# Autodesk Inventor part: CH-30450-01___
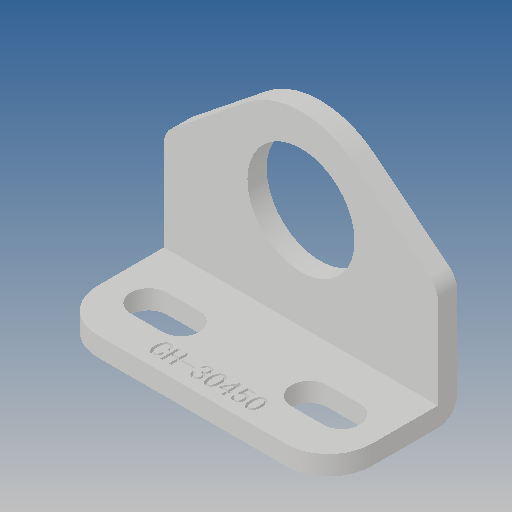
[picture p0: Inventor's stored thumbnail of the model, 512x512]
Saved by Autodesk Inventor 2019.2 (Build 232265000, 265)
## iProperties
Created: 2010-06
Part Number: CH-30450-01___
Material: Ogólny
Document SubType Name: Modeling
Designer: CADENGINEERING4
Density: 1 g/cm^3
Appearance: Domyślna
Author: CADENGINEERING4
Revision Number: ANY
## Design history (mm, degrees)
feature "NONE"
node "Bryła1"
